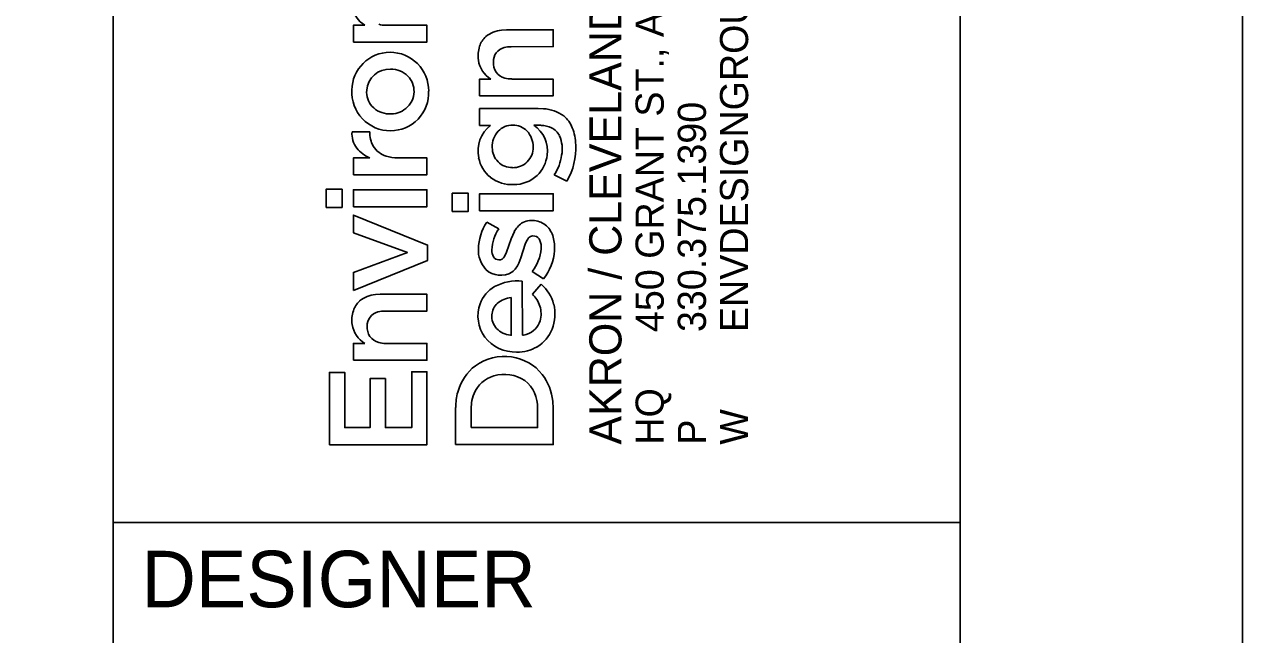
# Model space of a CAD drawing. Extents: x -0.5 to 34, y 0 to 22.
# Drawn here: x 31.843 to 34, y 2.302 to 3.382 of the extents above; entities that cross this region are included whole.
import ezdxf

# ---------------------------------------------------------------- set-up
doc = ezdxf.new("R2010")
doc.units = 0
for name, color, linetype in [('PM_X_CL_Double_Solid', 7, 'Continuous'), ('PM_X_Edge_Line', 7, 'Continuous'), ('PM_X_Transverse_Line', 7, 'Continuous')]:
    doc.layers.add(name, color=color, linetype=linetype)

msp = doc.modelspace()

# ---------------------------------------------------------------- linework, layer by layer
at = {"layer": 'PM_X_CL_Double_Solid'}
for p, q in [((32.4254, 3.3509), (32.4254, 3.3807)), ((32.4254, 3.3807), (32.4455, 3.3807)), ((32.4822, 3.3807), (32.5557, 3.3807)), ((32.5557, 3.3807), (32.5557, 3.351)), ((32.6878, 3.3722), (32.6963, 3.3727)), ((32.6963, 3.3727), (32.7792, 3.3727)), ((32.7792, 3.3727), (32.7792, 3.3429)), ((32.5557, 3.351), (32.4254, 3.3509)), ((32.7792, 3.3429), (32.7048, 3.3428)), ((32.6489, 3.2557), (32.6489, 3.2855)), ((32.6489, 3.2855), (32.669, 3.2855)), ((32.7057, 3.2855), (32.7791, 3.2855)), ((32.7791, 3.2855), (32.7792, 3.2558)), ((32.7792, 3.2558), (32.6489, 3.2557)), ((32.6489, 3.2034), (32.6489, 3.2332)), ((32.6489, 3.2332), (32.7524, 3.2332)), ((32.7524, 3.2332), (32.7619, 3.2329)), ((32.6684, 3.2034), (32.6489, 3.2034)), ((32.7576, 3.2036), (32.7449, 3.2036)), ((32.423, 3.1919), (32.4545, 3.1919)), ((32.4254, 3.1159), (32.4254, 3.1458)), ((32.4254, 3.1458), (32.4547, 3.1458)), ((32.5041, 3.1458), (32.5557, 3.1457)), ((32.5557, 3.1457), (32.5556, 3.1159)), ((32.5556, 3.1159), (32.4254, 3.1159)), ((32.8036, 3.1049), (32.7812, 3.116)), ((32.3771, 3.0582), (32.3771, 3.0903)), ((32.3771, 3.0903), (32.4054, 3.0903)), ((32.4054, 3.0903), (32.4054, 3.0582)), ((32.4254, 3.0594), (32.4254, 3.0893)), ((32.4254, 3.0893), (32.5557, 3.0893)), ((32.5557, 3.0893), (32.5557, 3.0594)), ((32.6005, 3.0511), (32.6005, 3.0832)), ((32.6005, 3.0832), (32.6289, 3.0832)), ((32.6289, 3.0832), (32.6289, 3.0511)), ((32.6489, 3.0523), (32.6489, 3.0822)), ((32.6489, 3.0822), (32.7792, 3.0822)), ((32.7792, 3.0822), (32.7792, 3.0523)), ((32.4054, 3.0582), (32.3771, 3.0582)), ((32.5557, 3.0594), (32.4254, 3.0594)), ((32.4254, 3.0133), (32.4254, 3.0446)), ((32.4254, 3.0446), (32.5567, 2.9913)), ((32.6289, 3.0511), (32.6005, 3.0511)), ((32.7792, 3.0523), (32.6489, 3.0523)), ((32.6615, 3.0321), (32.6827, 3.0203)), ((32.5212, 2.978), (32.4254, 3.0133)), ((32.6967, 2.9787), (32.7048, 3.0026)), ((32.7048, 3.0026), (32.7104, 3.0153)), ((32.7334, 3.001), (32.7298, 2.9933)), ((32.4254, 2.9429), (32.5212, 2.978)), ((32.5567, 2.9913), (32.5567, 2.9644)), ((32.693, 2.9712), (32.6967, 2.9787)), ((32.7298, 2.9933), (32.7221, 2.9688)), ((32.5567, 2.9644), (32.4254, 2.9109)), ((32.7221, 2.9688), (32.7182, 2.9592)), ((32.4254, 2.9109), (32.4254, 2.9429)), ((32.7621, 2.9314), (32.742, 2.9447)), ((32.7245, 2.9275), (32.7246, 2.8319)), ((32.7423, 2.9046), (32.7577, 2.922)), ((32.4644, 2.904), (32.4729, 2.9044)), ((32.4729, 2.9044), (32.5557, 2.9044)), ((32.5557, 2.9044), (32.5557, 2.8746)), ((32.7049, 2.8318), (32.7049, 2.8983)), ((32.5557, 2.8746), (32.4814, 2.8746)), ((32.7036, 2.8317), (32.7049, 2.8318)), ((32.4254, 2.7875), (32.4254, 2.8173)), ((32.4254, 2.8173), (32.4455, 2.8173)), ((32.4822, 2.8173), (32.5557, 2.8173)), ((32.5557, 2.8173), (32.5557, 2.7876)), ((32.5557, 2.7876), (32.4254, 2.7875)), ((32.383, 2.6379), (32.383, 2.766)), ((32.383, 2.766), (32.4101, 2.766)), ((32.4101, 2.766), (32.4101, 2.6683)), ((32.5286, 2.6683), (32.5286, 2.7672)), ((32.5286, 2.7672), (32.5557, 2.7672)), ((32.5557, 2.7672), (32.5557, 2.6379)), ((32.455, 2.6683), (32.455, 2.7549)), ((32.455, 2.7549), (32.4822, 2.7549)), ((32.4822, 2.7549), (32.4822, 2.6683)), ((32.6064, 2.638), (32.6064, 2.704)), ((32.6347, 2.7118), (32.6341, 2.7023)), ((32.6341, 2.7023), (32.6341, 2.6684)), ((32.7515, 2.6683), (32.7515, 2.7024)), ((32.7785, 2.715), (32.7792, 2.7021)), ((32.7792, 2.7021), (32.7792, 2.638)), ((32.4101, 2.6683), (32.455, 2.6683)), ((32.4822, 2.6683), (32.5286, 2.6683)), ((32.6341, 2.6684), (32.7515, 2.6683)), ((32.5557, 2.6379), (32.383, 2.6379)), ((32.7792, 2.638), (32.6064, 2.638))]:
    msp.add_line(p, q, dxfattribs=at)
for points in [[(32.4254, 3.3509), (32.4254, 3.3807), (32.4455, 3.3807)], [(32.4822, 3.3807), (32.5557, 3.3807), (32.5557, 3.351), (32.4254, 3.3509)], [(32.6878, 3.3722), (32.6963, 3.3727), (32.7792, 3.3727), (32.7792, 3.3429), (32.7048, 3.3428)], [(32.6489, 3.2557), (32.6489, 3.2855), (32.669, 3.2855)], [(32.7057, 3.2855), (32.7791, 3.2855), (32.7792, 3.2558), (32.6489, 3.2557)], [(32.6684, 3.2034), (32.6489, 3.2034), (32.6489, 3.2332), (32.7524, 3.2332), (32.7619, 3.2329)], [(32.7576, 3.2036), (32.7449, 3.2036)], [(32.423, 3.1919), (32.4545, 3.1919)], [(32.4254, 3.1159), (32.4254, 3.1458), (32.4547, 3.1458)], [(32.5041, 3.1458), (32.5557, 3.1457), (32.5556, 3.1159), (32.4254, 3.1159)], [(32.8036, 3.1049), (32.7812, 3.116)], [(32.6615, 3.0321), (32.6827, 3.0203)], [(32.693, 2.9712), (32.6967, 2.9787), (32.7048, 3.0026), (32.7104, 3.0153)], [(32.7334, 3.001), (32.7298, 2.9933), (32.7221, 2.9688), (32.7182, 2.9592)], [(32.7621, 2.9314), (32.742, 2.9447)], [(32.7245, 2.9275), (32.7246, 2.8319)], [(32.7423, 2.9046), (32.7577, 2.922)], [(32.4644, 2.904), (32.4729, 2.9044), (32.5557, 2.9044), (32.5557, 2.8746), (32.4814, 2.8746)], [(32.7036, 2.8317), (32.7049, 2.8318), (32.7049, 2.8983)], [(32.4254, 2.7875), (32.4254, 2.8173), (32.4455, 2.8173)], [(32.4822, 2.8173), (32.5557, 2.8173), (32.5557, 2.7876), (32.4254, 2.7875)], [(32.7785, 2.715), (32.7792, 2.7021), (32.7792, 2.638), (32.6064, 2.638)], [(32.6064, 2.638), (32.6064, 2.704)], [(32.6347, 2.7118), (32.6341, 2.7023), (32.6341, 2.6684), (32.7515, 2.6683), (32.7515, 2.7024)]]:
    msp.add_lwpolyline(points, dxfattribs=at)
for points in [[(32.3771, 3.0582), (32.3771, 3.0903), (32.4054, 3.0903), (32.4054, 3.0582)], [(32.4254, 3.0594), (32.4254, 3.0893), (32.5557, 3.0893), (32.5557, 3.0594)], [(32.6005, 3.0511), (32.6005, 3.0832), (32.6289, 3.0832), (32.6289, 3.0511)], [(32.6489, 3.0523), (32.6489, 3.0822), (32.7792, 3.0822), (32.7792, 3.0523)], [(32.4254, 2.9109), (32.4254, 2.9429), (32.5212, 2.978), (32.4254, 3.0133), (32.4254, 3.0446), (32.5567, 2.9913), (32.5567, 2.9644)], [(32.383, 2.6379), (32.383, 2.766), (32.4101, 2.766), (32.4101, 2.6683), (32.455, 2.6683), (32.455, 2.7549), (32.4822, 2.7549), (32.4822, 2.6683), (32.5286, 2.6683), (32.5286, 2.7672), (32.5557, 2.7672), (32.5557, 2.6379)]]:
    msp.add_lwpolyline(points, close=True, dxfattribs=at)
for centre, radius, start, end in [((32.4703, 3.4214), 0.0476, 188.9646, 238.6987), ((32.4703, 3.4214), 0.0476, 188.9646, 238.6987), ((32.4818, 3.4229), 0.0421, 254.0891, 270.5284), ((32.4818, 3.4229), 0.0421, 254.0891, 270.5284), ((32.6922, 3.3225), 0.0499, 94.9706, 130.2248), ((32.6922, 3.3225), 0.0499, 94.9706, 130.2248), ((32.6869, 3.3309), 0.0402, 132.2238, 161.6823), ((32.6869, 3.3309), 0.0402, 132.2238, 161.6823), ((32.4901, 3.2654), 0.0674, 89.8476, 179.6405), ((32.4901, 3.2654), 0.0674, 89.8476, 179.6405), ((32.4906, 3.2647), 0.0681, 359.5401, 90.2114), ((32.4906, 3.2647), 0.0681, 359.5401, 90.2114), ((32.7022, 3.3264), 0.056, 162.274, 187.7917), ((32.7022, 3.3264), 0.056, 162.274, 187.7917), ((32.6983, 3.3169), 0.025, 103.6868, 182.214), ((32.6983, 3.3169), 0.025, 103.6868, 182.214), ((32.7045, 3.2968), 0.046, 89.6051, 105.3303), ((32.7045, 3.2968), 0.046, 89.6051, 105.3303), ((32.4892, 3.2626), 0.0404, 87.0481, 175.5726), ((32.4892, 3.2626), 0.0404, 87.0481, 175.5726), ((32.492, 3.26), 0.043, 45.8426, 90.9801), ((32.492, 3.26), 0.043, 45.8426, 90.9801), ((32.6937, 3.3262), 0.0476, 188.9646, 238.6987), ((32.6937, 3.3262), 0.0476, 188.9646, 238.6987), ((32.7008, 3.3138), 0.0276, 175.5844, 255.1382), ((32.7008, 3.3138), 0.0276, 175.5844, 255.1382), ((32.4946, 3.2642), 0.0382, 357.8857, 44.159), ((32.4946, 3.2642), 0.0382, 357.8857, 44.159), ((32.7053, 3.3277), 0.0421, 254.0891, 270.5284), ((32.7053, 3.3277), 0.0421, 254.0891, 270.5284), ((32.4908, 3.2621), 0.0682, 176.8344, 270.4038), ((32.4908, 3.2621), 0.0682, 176.8344, 270.4038), ((32.4873, 3.2625), 0.0385, 175.1538, 221.1471), ((32.4873, 3.2625), 0.0385, 175.1538, 221.1471), ((32.4912, 3.2614), 0.0675, 270.0624, 2.3776), ((32.4912, 3.2614), 0.0675, 270.0624, 2.3776), ((32.4945, 3.2632), 0.0383, 308.2894, 359.4347), ((32.4945, 3.2632), 0.0383, 308.2894, 359.4347), ((32.4892, 3.2661), 0.0423, 223.0999, 268.8089), ((32.4892, 3.2661), 0.0423, 223.0999, 268.8089), ((32.491, 3.2679), 0.0442, 266.5651, 308.0608), ((32.491, 3.2679), 0.0442, 266.5651, 308.0608), ((32.7591, 3.1679), 0.065, 53.4034, 87.4906), ((32.7591, 3.1679), 0.065, 53.4034, 87.4906), ((32.7652, 3.1804), 0.0514, 21.6075, 50.5577), ((32.7652, 3.1804), 0.0514, 21.6075, 50.5577), ((32.7029, 3.1581), 0.0569, 127.3748, 192.2247), ((32.7029, 3.1581), 0.0569, 127.3748, 192.2247), ((32.7114, 3.166), 0.0401, 137.4674, 182.3324), ((32.7114, 3.166), 0.0401, 137.4674, 182.3324), ((32.7069, 3.1693), 0.0346, 88.473, 136.4256), ((32.7069, 3.1693), 0.0346, 88.473, 136.4256), ((32.7081, 3.1696), 0.0342, 44.2719, 90.4762), ((32.7081, 3.1696), 0.0342, 44.2719, 90.4762), ((32.7037, 3.166), 0.04, 358.5714, 43.5376), ((32.7037, 3.166), 0.04, 358.5714, 43.5376), ((32.7142, 3.1583), 0.0547, 352.1125, 55.923), ((32.7142, 3.1583), 0.0547, 352.1125, 55.923), ((32.7567, 3.1572), 0.0463, 65.0169, 88.8011), ((32.7567, 3.1572), 0.0463, 65.0169, 88.8011), ((32.7626, 3.1716), 0.0309, 26.2681, 63.803), ((32.7626, 3.1716), 0.0309, 26.2681, 63.803), ((32.7307, 3.1671), 0.0884, 1.1514, 21.3627), ((32.7307, 3.1671), 0.0884, 1.1514, 21.3627), ((32.4662, 3.1888), 0.0433, 175.8731, 216.3475), ((32.4662, 3.1888), 0.0433, 175.8731, 216.3475), ((32.5009, 3.1895), 0.0464, 176.9688, 209.6064), ((32.5009, 3.1895), 0.0464, 176.9688, 209.6064), ((32.7357, 3.1615), 0.0595, 349.3073, 23.4307), ((32.7357, 3.1615), 0.0595, 349.3073, 23.4307), ((32.4747, 3.1972), 0.0551, 218.0981, 248.7907), ((32.4747, 3.1972), 0.0551, 218.0981, 248.7907), ((32.4951, 3.1881), 0.0408, 211.9447, 253.2028), ((32.4951, 3.1881), 0.0408, 211.9447, 253.2028), ((32.7065, 3.1637), 0.0351, 178.8821, 271.0837), ((32.7065, 3.1637), 0.0351, 178.8821, 271.0837), ((32.7082, 3.164), 0.0355, 268.2788, 1.5502), ((32.7082, 3.164), 0.0355, 268.2788, 1.5502), ((32.7099, 3.1571), 0.0589, 313.742, 353.8554), ((32.7099, 3.1571), 0.0589, 313.742, 353.8554), ((32.7074, 3.1633), 0.0877, 327.3149, 351.5748), ((32.7074, 3.1633), 0.0877, 327.3149, 351.5748), ((32.7054, 3.1624), 0.1138, 329.6388, 3.26), ((32.7054, 3.1624), 0.1138, 329.6388, 3.26), ((32.5047, 3.2165), 0.0707, 252.4655, 269.573), ((32.5047, 3.2165), 0.0707, 252.4655, 269.573), ((32.7046, 3.157), 0.0584, 190.7518, 231.2892), ((32.7046, 3.157), 0.0584, 190.7518, 231.2892), ((32.7063, 3.1611), 0.0627, 232.4606, 272.5902), ((32.7063, 3.1611), 0.0627, 232.4606, 272.5902), ((32.7095, 3.159), 0.0605, 269.6361, 312.7088), ((32.7095, 3.159), 0.0605, 269.6361, 312.7088), ((32.7364, 2.9826), 0.0897, 146.531, 178.7571), ((32.7364, 2.9826), 0.0897, 146.531, 178.7571), ((32.7452, 2.9789), 0.0749, 146.5112, 176.9101), ((32.7452, 2.9789), 0.0749, 146.5112, 176.9101), ((32.7466, 2.9971), 0.0405, 125.5118, 153.4159), ((32.7466, 2.9971), 0.0405, 125.5118, 153.4159), ((32.7406, 3.0026), 0.0326, 80.1719, 122.5197), ((32.7406, 3.0026), 0.0326, 80.1719, 122.5197), ((32.7428, 2.9982), 0.0367, 47.7934, 84.6892), ((32.7428, 2.9982), 0.0367, 47.7934, 84.6892), ((32.7379, 2.9946), 0.0427, 14.9966, 46.2063), ((32.7379, 2.9946), 0.0427, 14.9966, 46.2063), ((32.7438, 2.9963), 0.0114, 76.6609, 155.7053), ((32.7438, 2.9963), 0.0114, 76.6609, 155.7053), ((32.744, 2.9951), 0.0126, 21.5098, 78.5262), ((32.744, 2.9951), 0.0126, 21.5098, 78.5262), ((32.7259, 2.9877), 0.0321, 354.5726, 22.068), ((32.7259, 2.9877), 0.0321, 354.5726, 22.068), ((32.7104, 2.9867), 0.0712, 355.8306, 15.3914), ((32.7104, 2.9867), 0.0712, 355.8306, 15.3914), ((32.6967, 2.9824), 0.0501, 177.5366, 222.7932), ((32.6967, 2.9824), 0.0501, 177.5366, 222.7932), ((32.6931, 2.9823), 0.0228, 178.4747, 211.0868), ((32.6931, 2.9823), 0.0228, 178.4747, 211.0868), ((32.6825, 2.9915), 0.0757, 321.811, 354.7969), ((32.6825, 2.9915), 0.0757, 321.811, 354.7969), ((32.6895, 2.9882), 0.0922, 321.9777, 355.8738), ((32.6895, 2.9882), 0.0922, 321.9777, 355.8738), ((32.6833, 2.9767), 0.0115, 212.2368, 268.3777), ((32.6833, 2.9767), 0.0115, 212.2368, 268.3777), ((32.6834, 2.9759), 0.0107, 267.716, 333.7337), ((32.6834, 2.9759), 0.0107, 267.716, 333.7337), ((32.681, 2.9758), 0.0408, 308.0877, 335.9874), ((32.681, 2.9758), 0.0408, 308.0877, 335.9874), ((32.686, 2.9753), 0.0375, 225.9854, 302.4797), ((32.686, 2.9753), 0.0375, 225.9854, 302.4797), ((32.7024, 2.8691), 0.0558, 118.8308, 160.6244), ((32.7024, 2.8691), 0.0558, 118.8308, 160.6244), ((32.7152, 2.8441), 0.0838, 83.615, 118.2876), ((32.7152, 2.8441), 0.0838, 83.615, 118.2876), ((32.7174, 2.8717), 0.0644, 13.5336, 51.3615), ((32.7174, 2.8717), 0.0644, 13.5336, 51.3615), ((32.4635, 2.8626), 0.0402, 132.2219, 161.6818), ((32.4635, 2.8626), 0.0402, 132.2219, 161.6818), ((32.4687, 2.8543), 0.0499, 94.9696, 130.2225), ((32.4687, 2.8543), 0.0499, 94.9696, 130.2225), ((32.7079, 2.8561), 0.0424, 94.008, 130.8817), ((32.7079, 2.8561), 0.0424, 94.008, 130.8817), ((32.7038, 2.8656), 0.0549, 19.0357, 45.4406), ((32.7038, 2.8656), 0.0549, 19.0357, 45.4406), ((32.4787, 2.8582), 0.056, 162.2736, 187.7919), ((32.4787, 2.8582), 0.056, 162.2736, 187.7919), ((32.4748, 2.8487), 0.025, 103.6865, 182.2187), ((32.4748, 2.8487), 0.025, 103.6865, 182.2187), ((32.4811, 2.8286), 0.046, 89.6049, 105.3284), ((32.4811, 2.8286), 0.046, 89.6049, 105.3284), ((32.7104, 2.8661), 0.0644, 160.5201, 215.7831), ((32.7104, 2.8661), 0.0644, 160.5201, 215.7831), ((32.7005, 2.8663), 0.0298, 132.9851, 177.179), ((32.7005, 2.8663), 0.0298, 132.9851, 177.179), ((32.7107, 2.8697), 0.047, 344.6059, 17.007), ((32.7107, 2.8697), 0.047, 344.6059, 17.007), ((32.7064, 2.8692), 0.0758, 339.3542, 13.3785), ((32.7064, 2.8692), 0.0758, 339.3542, 13.3785), ((32.4703, 2.858), 0.0476, 188.962, 238.7037), ((32.4703, 2.858), 0.0476, 188.962, 238.7037), ((32.4773, 2.8456), 0.0276, 175.5854, 255.1439), ((32.4773, 2.8456), 0.0276, 175.5854, 255.1439), ((32.7017, 2.865), 0.0311, 175.0013, 223.283), ((32.7017, 2.865), 0.0311, 175.0013, 223.283), ((32.7224, 2.8671), 0.035, 288.0077, 343.5508), ((32.7224, 2.8671), 0.035, 288.0077, 343.5508), ((32.7125, 2.8705), 0.0687, 217.7452, 271.6543), ((32.7125, 2.8705), 0.0687, 217.7452, 271.6543), ((32.7089, 2.8736), 0.0423, 225.0619, 262.7974), ((32.7089, 2.8736), 0.0423, 225.0619, 262.7974), ((32.7247, 2.8522), 0.0202, 269.7003, 294.8711), ((32.7247, 2.8522), 0.0202, 269.7003, 294.8711), ((32.7189, 2.8652), 0.0626, 300.9427, 338.7323), ((32.7189, 2.8652), 0.0626, 300.9427, 338.7323), ((32.4818, 2.8595), 0.0422, 254.0916, 270.5284), ((32.4818, 2.8595), 0.0422, 254.0916, 270.5284), ((32.7155, 2.8724), 0.0706, 269.2048, 300.3341), ((32.7155, 2.8724), 0.0706, 269.2048, 300.3341), ((32.6923, 2.7079), 0.0864, 81.194, 125.9984), ((32.6923, 2.7079), 0.0864, 81.194, 125.9984), ((32.6946, 2.7113), 0.0827, 37.8521, 82.402), ((32.6946, 2.7113), 0.0827, 37.8521, 82.402), ((32.6939, 2.7089), 0.0865, 127.2362, 165.148), ((32.6939, 2.7089), 0.0865, 127.2362, 165.148), ((32.6928, 2.6986), 0.0639, 55.6727, 107.2093), ((32.6928, 2.6986), 0.0639, 55.6727, 107.2093), ((32.6859, 2.7057), 0.0931, 5.7333, 37.304), ((32.6859, 2.7057), 0.0931, 5.7333, 37.304), ((32.6889, 2.7078), 0.054, 106.1881, 157.3861), ((32.6889, 2.7078), 0.054, 106.1881, 157.3861), ((32.6929, 2.705), 0.0587, 357.4662, 52.2665), ((32.6929, 2.705), 0.0587, 357.4662, 52.2665), ((32.7143, 2.7028), 0.1078, 164.7861, 179.3704), ((32.7143, 2.7028), 0.1078, 164.7861, 179.3704), ((32.6983, 2.7039), 0.0641, 157.3571, 172.9275), ((32.6983, 2.7039), 0.0641, 157.3571, 172.9275)]:
    msp.add_arc(centre, radius, start, end, dxfattribs=at)
at = {"layer": 'PM_X_Edge_Line'}
msp.add_lwpolyline([(0, 0), (34, 0), (34, 22), (0, 22)], close=True, dxfattribs=at)
at = {"layer": 'PM_X_Transverse_Line'}
for p, q in [((32, 0.5), (32, 21.5)), ((32, 2.5), (33.5, 2.5))]:
    msp.add_line(p, q, dxfattribs=at)
msp.add_lwpolyline([(1.5, 21.5), (33.5, 21.5), (33.5, 0.5), (1.5, 0.5)], close=True, dxfattribs=at)

# ---------------------------------------------------------------- texts
at = {"layer": 'PM_X_CL_Double_Solid'}
for s, height, p in [('450 GRANT ST., AKRON, OH  44311', 0.049846, (32.9749, 2.8374)), ('AKRON / CLEVELAND / COLUMBUS', 0.056969, (32.9001, 2.638)), ('ENVDESIGNGROUP.COM', 0.049846, (33.1244, 2.8374)), ('330.375.1390', 0.049846, (33.0497, 2.8374)), ('HQ ', 0.04985, (32.9749, 2.638)), ('W', 0.0498, (33.1244, 2.638)), ('P', 0.0498, (33.0497, 2.638))]:
    msp.add_text(s, height=height, rotation=90, dxfattribs=at).set_placement(p)
msp.add_text('DESIGNER', height=0.1, dxfattribs=at).set_placement((32.05, 2.35))

doc.saveas('drawing.dxf')
